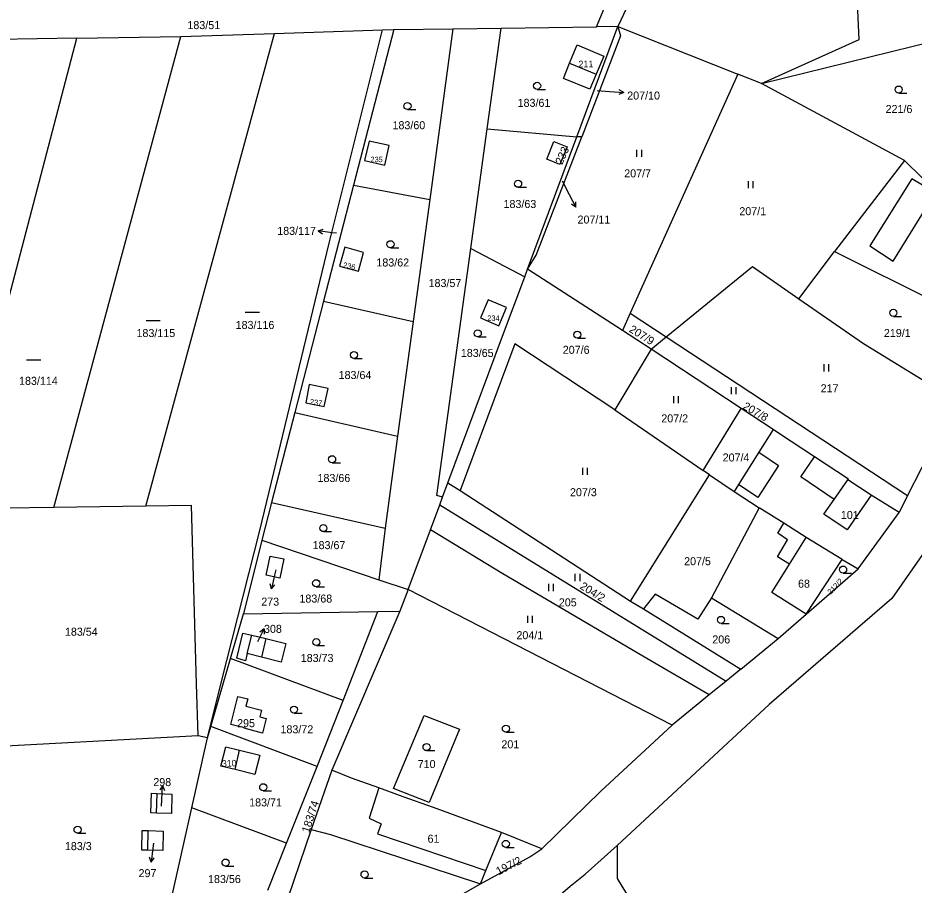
# Model space of a CAD drawing. Extents: x -7483133 to -743169, y -11317770 to -1127091.
# Drawn here: x -746832.8 to -746642.5, y -1132263.2 to -1132079.1 of the extents above; entities that cross this region are included whole.
import ezdxf

# ---------------------------------------------------------------- set-up
doc = ezdxf.new("R2010")
doc.units = 0
for name, color, linetype in [('Hranice parcel', 7, 'Continuous'), ('Parcelní čísla', 7, 'Continuous'), ('Pop  PČ popisy', 7, 'Continuous'), ('Vnitřní kresba', 7, 'Continuous'), ('Značky kultur', 7, 'Continuous')]:
    doc.layers.add(name, color=color, linetype=linetype)

msp = doc.modelspace()

# ---------------------------------------------------------------- linework, layer by layer
at = {"layer": 'Hranice parcel'}
for p, q in [((-746778.25, -1132082.36), (-746755.32, -1132081.61)), ((-746752.93, -1132081.53), (-746761.49, -1132114.56)), ((-746755.32, -1132081.61), (-746752.93, -1132081.53)), ((-746752.93, -1132081.53), (-746740.4, -1132081.38)), ((-746740.4, -1132081.38), (-746745.32, -1132117.64)), ((-746740.4, -1132081.38), (-746730.14, -1132081.25)), ((-746733.1, -1132102.66), (-746730.14, -1132081.25)), ((-746730.14, -1132081.25), (-746709.89, -1132080.97)), ((-746714.1, -1132104.36), (-746705.38, -1132080.91)), ((-746705.38, -1132080.91), (-746709.89, -1132080.97)), ((-746705.38, -1132080.91), (-746679.89, -1132091)), ((-746705.38, -1132080.91), (-746704.8, -1132082.86)), ((-746820.24, -1132083.39), (-746845.06, -1132083.8)), ((-746825.13, -1132182.99), (-746798.2, -1132083.02)), ((-746820.24, -1132083.39), (-746798.2, -1132083.02)), ((-746805.63, -1132182.7), (-746778.25, -1132082.36)), ((-746798.2, -1132083.02), (-746778.25, -1132082.36)), ((-746704.8, -1132082.86), (-746713.07, -1132104.3)), ((-746674.91, -1132092.97), (-746635.72, -1132083.37)), ((-746679.89, -1132091), (-746702.74, -1132141.73)), ((-746674.91, -1132092.97), (-746679.89, -1132091)), ((-746644.51, -1132109.35), (-746674.91, -1132092.97)), ((-746736.6, -1132128.06), (-746733.1, -1132102.66)), ((-746733.1, -1132102.66), (-746714.1, -1132104.36)), ((-746724.55, -1132132.39), (-746714.1, -1132104.36)), ((-746713.07, -1132104.3), (-746714.1, -1132104.36)), ((-746644.51, -1132109.35), (-746659.43, -1132128.69)), ((-746640.76, -1132113.05), (-746644.51, -1132109.35)), ((-746761.49, -1132114.56), (-746767.86, -1132139.21)), ((-746761.49, -1132114.56), (-746745.32, -1132117.64)), ((-746745.32, -1132117.64), (-746748.85, -1132143.55)), ((-746743.8, -1132180.44), (-746736.6, -1132128.06)), ((-746736.6, -1132128.06), (-746725.17, -1132134.06)), ((-746666.94, -1132138.69), (-746659.43, -1132128.69)), ((-746659.43, -1132128.69), (-746625.72, -1132145.44)), ((-746725.17, -1132134.06), (-746724.55, -1132132.39)), ((-746704.42, -1132145.46), (-746724.55, -1132132.39)), ((-746767.86, -1132139.21), (-746773.98, -1132162.83)), ((-746767.86, -1132139.21), (-746748.85, -1132143.55)), ((-746702.74, -1132141.73), (-746704.42, -1132145.46)), ((-746702.74, -1132141.73), (-746695.1, -1132146.75)), ((-746748.85, -1132143.55), (-746752.17, -1132167.89)), ((-746698.35, -1132149.4), (-746704.42, -1132145.46)), ((-746698.35, -1132149.4), (-746695.1, -1132146.75)), ((-746695.1, -1132146.75), (-746643.87, -1132180.43)), ((-746698.35, -1132149.4), (-746706, -1132162.26)), ((-746679.2, -1132162.02), (-746698.35, -1132149.4)), ((-746633.63, -1132160.23), (-746643.87, -1132180.43)), ((-746773.98, -1132162.83), (-746778.93, -1132181.95)), ((-746773.98, -1132162.83), (-746752.17, -1132167.89)), ((-746706, -1132162.26), (-746687.28, -1132175.19)), ((-746687.28, -1132175.19), (-746679.2, -1132162.02)), ((-746672.44, -1132166.48), (-746679.2, -1132162.02)), ((-746752.17, -1132167.89), (-746754.82, -1132187.37)), ((-746685.93, -1132176.1), (-746687.28, -1132175.19)), ((-746702.69, -1132202.89), (-746685.93, -1132176.1)), ((-746685.93, -1132176.1), (-746680.69, -1132179.58)), ((-746742.61, -1132180.85), (-746741.45, -1132177.74)), ((-746741.45, -1132177.74), (-746738.86, -1132179.39)), ((-746742.61, -1132180.85), (-746743.8, -1132180.44)), ((-746743.19, -1132182.42), (-746742.61, -1132180.85)), ((-746738.86, -1132179.39), (-746702.69, -1132202.89)), ((-746680.69, -1132179.58), (-746675.38, -1132183.11)), ((-746643.87, -1132180.43), (-746645.7, -1132184.06)), ((-746805.63, -1132182.7), (-746825.13, -1132182.99)), ((-746778.93, -1132181.95), (-746781, -1132189.93)), ((-746778.93, -1132181.95), (-746754.82, -1132187.37)), ((-746745.18, -1132187.75), (-746743.19, -1132182.42)), ((-746743.19, -1132182.42), (-746682.41, -1132219.89)), ((-746675.38, -1132183.11), (-746685.49, -1132202.16)), ((-746654.39, -1132196.03), (-746645.7, -1132184.06)), ((-746754.82, -1132187.37), (-746756.13, -1132198.33)), ((-746749.91, -1132200.43), (-746745.18, -1132187.75)), ((-746781, -1132189.93), (-746784.83, -1132205.6)), ((-746781, -1132189.93), (-746756.13, -1132198.33)), ((-746665.44, -1132205.68), (-746657.77, -1132194.04)), ((-746657.77, -1132194.04), (-746654.39, -1132196.03)), ((-746665.44, -1132205.68), (-746654.39, -1132196.03)), ((-746756.13, -1132198.33), (-746749.91, -1132200.43)), ((-746749.91, -1132200.43), (-746751.65, -1132205.03)), ((-746693.83, -1132229.18), (-746749.91, -1132200.43)), ((-746702.69, -1132202.89), (-746699.96, -1132204.52)), ((-746685.49, -1132202.16), (-746671.39, -1132210.8)), ((-746787.59, -1132215.05), (-746784.83, -1132205.6)), ((-746784.83, -1132205.6), (-746756.31, -1132205.11)), ((-746751.65, -1132205.03), (-746766.12, -1132238.78)), ((-746763.69, -1132223.97), (-746756.31, -1132205.11)), ((-746756.31, -1132205.11), (-746751.65, -1132205.03)), ((-746699.96, -1132204.52), (-746679.29, -1132217.36)), ((-746671.39, -1132210.8), (-746665.44, -1132205.68)), ((-746679.29, -1132217.36), (-746671.39, -1132210.8)), ((-746791.83, -1132229.53), (-746787.59, -1132215.05)), ((-746763.69, -1132223.97), (-746787.59, -1132215.05)), ((-746679.29, -1132217.36), (-746682.41, -1132219.89)), ((-746682.41, -1132219.89), (-746686, -1132222.81)), ((-746769.22, -1132238.01), (-746763.69, -1132223.97)), ((-746686, -1132222.81), (-746693.83, -1132229.18)), ((-746792.52, -1132231.9), (-746791.83, -1132229.53)), ((-746769.22, -1132238.01), (-746791.83, -1132229.53)), ((-746795.83, -1132246.75), (-746792.52, -1132231.9)), ((-746792.52, -1132231.9), (-746794.52, -1132231.47)), ((-746775.72, -1132254.29), (-746769.22, -1132238.01)), ((-746766.12, -1132238.78), (-746770.48, -1132251.33)), ((-746801.64, -1132272.79), (-746795.83, -1132246.75)), ((-746775.72, -1132254.29), (-746795.83, -1132246.75)), ((-746721.51, -1132255.46), (-746730.11, -1132251.98)), ((-746779.69, -1132264.25), (-746775.72, -1132254.29)), ((-746739.61, -1132265.77), (-746734.54, -1132262.91))]:
    msp.add_line(p, q, dxfattribs=at)
for points in [[(-746709.89, -1132080.97), (-746700.88, -1132059.24), (-746690.31, -1132034.95), (-746646.39, -1131931.6)], [(-746640.16, -1131931.3), (-746678.35, -1132019.74), (-746690.91, -1132050.15), (-746705.38, -1132080.91)], [(-746674.91, -1132092.97), (-746654.17, -1132083.68), (-746655.72, -1132049.5), (-746655.89, -1132035.79), (-746596.68, -1131997.54)], [(-746792.52, -1132231.9), (-746789.57, -1132220.24), (-746781.38, -1132187.88), (-746766.7, -1132126.93), (-746755.32, -1132081.61)], [(-746858.02, -1132224.47), (-746835.83, -1132142.89), (-746820.24, -1132083.39)], [(-746711.32, -1132094.22), (-746716.94, -1132091.93), (-746715.63, -1132088.71), (-746714.06, -1132084.83), (-746708.4, -1132087.18), (-746709.98, -1132090.99), (-746711.32, -1132094.22)], [(-746724.55, -1132132.39), (-746722.76, -1132129.43), (-746713.07, -1132104.3)], [(-746753.94, -1132106.19), (-746758.21, -1132105.23), (-746759.16, -1132109.33), (-746754.88, -1132110.32), (-746753.94, -1132106.19)], [(-746718.96, -1132105.32), (-746716.14, -1132106.48), (-746717.68, -1132110.21), (-746720.5, -1132109.04), (-746718.96, -1132105.32)], [(-746764.45, -1132131.77), (-746760.45, -1132132.87), (-746759.36, -1132128.86), (-746763.36, -1132127.77), (-746764.45, -1132131.77)], [(-746695.1, -1132146.75), (-746676.81, -1132131.86), (-746666.94, -1132138.69)], [(-746741.45, -1132177.74), (-746729.85, -1132146.61), (-746725.17, -1132134.06)], [(-746732.9, -1132138.91), (-746734.55, -1132142.77), (-746730.68, -1132144.42), (-746729.03, -1132140.57), (-746732.9, -1132138.91)], [(-746666.94, -1132138.69), (-746653.23, -1132148.18), (-746633.63, -1132160.23)], [(-746706, -1132162.26), (-746727.28, -1132148.3), (-746738.86, -1132179.39)], [(-746770.91, -1132156.92), (-746771.66, -1132160.8), (-746767.74, -1132161.56), (-746766.92, -1132157.72), (-746770.91, -1132156.92)], [(-746672.44, -1132166.48), (-746675.45, -1132171.26), (-746679.79, -1132178.16), (-746680.69, -1132179.58)], [(-746645.7, -1132184.06), (-746651.6, -1132180.37), (-746656.53, -1132177.13), (-746656.42, -1132176.97), (-746663.67, -1132172.26), (-746671.09, -1132167.37), (-746672.44, -1132166.48)], [(-746627.53, -1132169.14), (-746637.59, -1132188.53), (-746647.21, -1132202.3), (-746673.25, -1132224.8), (-746705.52, -1132254.75)], [(-746794.52, -1132231.47), (-746794.83, -1132220.45), (-746795.89, -1132182.56), (-746805.63, -1132182.7)], [(-746825.13, -1132182.99), (-746845.75, -1132183.3), (-746844.91, -1132224.19)], [(-746657.77, -1132194.04), (-746665.4, -1132189.36), (-746670.13, -1132186.36), (-746675.38, -1132183.11)], [(-746686, -1132222.81), (-746700.07, -1132214.57), (-746729.82, -1132197.08), (-746745.18, -1132187.75)], [(-746779.23, -1132193.32), (-746776.31, -1132193.91), (-746777.12, -1132197.98), (-746780.05, -1132197.37), (-746779.23, -1132193.32)], [(-746685.49, -1132202.16), (-746688.44, -1132206.74), (-746697.45, -1132201.42), (-746699.96, -1132204.52)], [(-746783.07, -1132210.11), (-746780.12, -1132210.8), (-746775.87, -1132211.89), (-746776.88, -1132215.82), (-746781.07, -1132214.77), (-746784.07, -1132214.03), (-746784.43, -1132215.59), (-746786.31, -1132214.99), (-746785, -1132209.67), (-746783.07, -1132210.11)], [(-746794.52, -1132231.47), (-746844.62, -1132234.18), (-746844.91, -1132224.19)], [(-746780.82, -1132230.88), (-746784.71, -1132229.88), (-746784.68, -1132229.78), (-746787.58, -1132229.04), (-746786.06, -1132223.12), (-746783.97, -1132223.66), (-746784.36, -1132225.19), (-746781.01, -1132226.05), (-746781.38, -1132227.48), (-746780.03, -1132227.83), (-746780.82, -1132230.88)], [(-746746.53, -1132227.19), (-746739, -1132230.07), (-746745.42, -1132245.64), (-746753.02, -1132242.69), (-746746.53, -1132227.19)], [(-746721.51, -1132255.46), (-746709.03, -1132243.21), (-746693.83, -1132229.18)], [(-746785.69, -1132234.52), (-746781.4, -1132235.6), (-746782.44, -1132239.69), (-746786.66, -1132238.64), (-746789.66, -1132237.89), (-746788.62, -1132233.78), (-746785.69, -1132234.52)], [(-746730.11, -1132251.98), (-746744.54, -1132246.69), (-746750.97, -1132244.4), (-746756.12, -1132242.54), (-746761.95, -1132240.48), (-746766.12, -1132238.78)], [(-746803.22, -1132243.72), (-746800.06, -1132243.84), (-746800.18, -1132248), (-746803.33, -1132247.87), (-746804.5, -1132247.82), (-746804.37, -1132243.68), (-746803.22, -1132243.72)], [(-746801.92, -1132251.69), (-746801.99, -1132255.84), (-746805.19, -1132255.76), (-746806.42, -1132255.73), (-746806.38, -1132251.58), (-746805.12, -1132251.61), (-746801.92, -1132251.69)], [(-746770.48, -1132251.33), (-746776.66, -1132269.51), (-746771.04, -1132270.84)], [(-746770.48, -1132251.33), (-746766.36, -1132252.44), (-746734.54, -1132262.91)], [(-746734.54, -1132262.91), (-746733.4, -1132260.05), (-746730.11, -1132251.98)], [(-746733.81, -1132276.07), (-746730.72, -1132274.13), (-746718.09, -1132265.55), (-746715.48, -1132263.41), (-746712.32, -1132260.82), (-746705.52, -1132254.75)], [(-746705.52, -1132254.75), (-746705.52, -1132261.75), (-746702.56, -1132266.68), (-746651.51, -1132285.68), (-746635.38, -1132289.23)], [(-746734.54, -1132262.91), (-746724.11, -1132257.19), (-746721.51, -1132255.46)]]:
    msp.add_lwpolyline(points, dxfattribs=at)
at = {"layer": 'Pop  PČ popisy'}
for p, q in [((-746709.8, -1132094.52), (-746707.14, -1132094.71)), ((-746707.14, -1132094.71), (-746704.15, -1132094.92)), ((-746704.15, -1132094.92), (-746705.18, -1132095.35)), ((-746704.15, -1132094.92), (-746705.11, -1132094.35)), ((-746717.22, -1132113.7), (-746715.7, -1132116.6)), ((-746715.7, -1132116.6), (-746714.29, -1132119.25)), ((-746714.29, -1132119.25), (-746714.32, -1132118.13)), ((-746714.29, -1132119.25), (-746715.2, -1132118.6)), ((-746769.02, -1132124.26), (-746767.96, -1132123.91)), ((-746766.05, -1132124.68), (-746769.02, -1132124.26)), ((-746769.02, -1132124.26), (-746768.1, -1132124.9)), ((-746765.15, -1132124.8), (-746766.05, -1132124.68)), ((-746778.25, -1132197.36), (-746778.93, -1132200.28)), ((-746777.98, -1132196.22), (-746778.25, -1132197.36)), ((-746778.93, -1132200.28), (-746779.19, -1132199.2)), ((-746778.93, -1132200.28), (-746778.21, -1132199.42)), ((-746781.83, -1132211.46), (-746780.51, -1132208.76)), ((-746780.51, -1132208.76), (-746781.4, -1132209.44)), ((-746780.51, -1132208.76), (-746780.5, -1132209.88)), ((-746802.05, -1132242.04), (-746802.6, -1132243.02)), ((-746802.21, -1132245.04), (-746802.05, -1132242.04)), ((-746802.05, -1132242.04), (-746801.6, -1132243.07)), ((-746802.29, -1132246.38), (-746802.21, -1132245.04)), ((-746803.94, -1132254.29), (-746804.08, -1132255.35)), ((-746804.08, -1132255.35), (-746804.45, -1132258.33)), ((-746804.45, -1132258.33), (-746804.82, -1132257.27)), ((-746804.45, -1132258.33), (-746803.83, -1132257.4))]:
    msp.add_line(p, q, dxfattribs=at)
at = {"layer": 'Vnitřní kresba'}
for p, q in [((-746715.63, -1132088.71), (-746709.98, -1132090.99)), ((-746642.98, -1132113.24), (-746651.88, -1132127.45)), ((-746637.99, -1132116.23), (-746642.98, -1132113.24)), ((-746646.97, -1132130.75), (-746637.99, -1132116.23)), ((-746651.88, -1132127.45), (-746646.97, -1132130.75)), ((-746675.45, -1132171.26), (-746671.27, -1132174.11)), ((-746666.56, -1132176.49), (-746663.67, -1132172.26)), ((-746671.27, -1132174.11), (-746675.65, -1132180.87)), ((-746659.47, -1132181.31), (-746666.56, -1132176.49)), ((-746675.65, -1132180.87), (-746679.79, -1132178.16)), ((-746659.47, -1132181.31), (-746656.53, -1132177.13)), ((-746651.6, -1132180.37), (-746656.68, -1132187.78)), ((-746661.63, -1132184.39), (-746659.47, -1132181.31)), ((-746656.68, -1132187.78), (-746661.63, -1132184.39)), ((-746671.46, -1132188.47), (-746670.13, -1132186.36)), ((-746669.35, -1132189.9), (-746671.46, -1132188.47)), ((-746671.5, -1132193.47), (-746669.35, -1132189.9)), ((-746668.98, -1132195.04), (-746665.4, -1132189.36)), ((-746668.98, -1132195.04), (-746671.5, -1132193.47)), ((-746672.69, -1132201.07), (-746668.98, -1132195.04)), ((-746665.44, -1132205.68), (-746672.69, -1132201.07)), ((-746784.07, -1132214.03), (-746783.07, -1132210.11)), ((-746780.12, -1132210.8), (-746781.07, -1132214.77)), ((-746786.66, -1132238.64), (-746785.69, -1132234.52)), ((-746756.12, -1132242.54), (-746758.19, -1132248.97)), ((-746803.33, -1132247.87), (-746803.22, -1132243.72)), ((-746758.19, -1132248.97), (-746755.61, -1132250.15)), ((-746755.61, -1132250.15), (-746756.42, -1132252.29)), ((-746805.19, -1132255.76), (-746805.12, -1132251.61)), ((-746756.42, -1132252.29), (-746733.4, -1132260.05))]:
    msp.add_line(p, q, dxfattribs=at)
at = {"layer": 'Značky kultur'}
for p, q in [((-746722.52, -1132094.25), (-746720.77, -1132094.25)), ((-746645.77, -1132095.04), (-746644.02, -1132095.04)), ((-746750.05, -1132098.54), (-746748.3, -1132098.54)), ((-746701.33, -1132108.56), (-746701.33, -1132107.06)), ((-746700.33, -1132108.56), (-746700.33, -1132107.06)), ((-746677.68, -1132115.25), (-746677.68, -1132113.75)), ((-746676.68, -1132115.25), (-746676.68, -1132113.75)), ((-746726.56, -1132115.04), (-746724.81, -1132115.04)), ((-746753.66, -1132127.87), (-746751.91, -1132127.87)), ((-746784.5, -1132141.56), (-746781.5, -1132141.56)), ((-746646.9, -1132142.44), (-746645.15, -1132142.44)), ((-746805.52, -1132143.28), (-746802.52, -1132143.28)), ((-746735.13, -1132146.8), (-746733.38, -1132146.8)), ((-746713.99, -1132147.08), (-746712.24, -1132147.08)), ((-746830.92, -1132151.63), (-746827.92, -1132151.63)), ((-746761.41, -1132151.38), (-746759.66, -1132151.38)), ((-746661.58, -1132154.11), (-746661.58, -1132152.61)), ((-746660.58, -1132154.11), (-746660.58, -1132152.61)), ((-746681.27, -1132158.98), (-746681.27, -1132157.48)), ((-746680.27, -1132158.98), (-746680.27, -1132157.48)), ((-746693.52, -1132160.87), (-746693.52, -1132159.37)), ((-746692.52, -1132160.87), (-746692.52, -1132159.37)), ((-746766.05, -1132173.51), (-746764.3, -1132173.51)), ((-746712.83, -1132176.07), (-746712.83, -1132174.57)), ((-746711.83, -1132176.07), (-746711.83, -1132174.57)), ((-746767.9, -1132188.13), (-746766.15, -1132188.13)), ((-746714.42, -1132198.62), (-746714.42, -1132197.12)), ((-746713.42, -1132198.62), (-746713.42, -1132197.12)), ((-746657.57, -1132196.93), (-746655.82, -1132196.93)), ((-746769.43, -1132199.84), (-746767.68, -1132199.84)), ((-746720.06, -1132200.74), (-746720.06, -1132199.24)), ((-746719.06, -1132200.74), (-746719.06, -1132199.24)), ((-746724.48, -1132207.5), (-746724.48, -1132206)), ((-746723.48, -1132207.5), (-746723.48, -1132206)), ((-746683.49, -1132207.62), (-746681.74, -1132207.62)), ((-746769.4, -1132212.32), (-746767.65, -1132212.32)), ((-746774.14, -1132226.66), (-746772.39, -1132226.66)), ((-746729.16, -1132230.7), (-746727.41, -1132230.7)), ((-746746, -1132234.62), (-746744.25, -1132234.62)), ((-746780.68, -1132243.14), (-746778.93, -1132243.14)), ((-746820.09, -1132252.15), (-746818.34, -1132252.15)), ((-746729.17, -1132255.17), (-746727.42, -1132255.17)), ((-746788.67, -1132259.13), (-746786.92, -1132259.13)), ((-746759.16, -1132261.66), (-746757.41, -1132261.66))]:
    msp.add_line(p, q, dxfattribs=at)
for centre in [(-746722.52, -1132093.5), (-746645.77, -1132094.29), (-746750.05, -1132097.79), (-746726.56, -1132114.29), (-746753.66, -1132127.12), (-746646.9, -1132141.69), (-746735.13, -1132146.05), (-746713.99, -1132146.33), (-746761.41, -1132150.63), (-746766.05, -1132172.76), (-746767.9, -1132187.38), (-746657.57, -1132196.18), (-746769.43, -1132199.09), (-746683.49, -1132206.87), (-746769.4, -1132211.57), (-746774.14, -1132225.91), (-746729.16, -1132229.95), (-746746, -1132233.87), (-746780.68, -1132242.39), (-746820.09, -1132251.4), (-746729.17, -1132254.42), (-746788.67, -1132258.38), (-746759.16, -1132260.91)]:
    msp.add_circle(centre, 0.75, dxfattribs=at)

# ---------------------------------------------------------------- texts
at = {"layer": 'Parcelní čísla'}
for s, height, p in [('183/51', 1.7, (-746796.77, -1132081.46)), ('207/10', 1.7, (-746703.4, -1132096.41)), ('183/61', 1.7, (-746726.67, -1132097.96)), ('221/6', 1.7, (-746648.55, -1132099.27)), ('183/60', 1.7, (-746753.23, -1132102.71)), ('235', 1.14, (-746757.92, -1132109.7)), ('207/7', 1.7, (-746704.04, -1132112.93)), ('183/63', 1.7, (-746729.66, -1132119.43)), ('207/1', 1.7, (-746679.6, -1132120.96)), ('207/11', 1.7, (-746713.95, -1132122.74)), ('183/117', 1.7, (-746777.7, -1132125.14)), ('183/62', 1.7, (-746756.65, -1132131.85)), ('183/57', 1.7, (-746745.57, -1132136.22)), ('234', 1.14, (-746733.11, -1132143.39)), ('183/116', 1.7, (-746786.53, -1132145.11)), ('183/115', 1.7, (-746807.58, -1132146.83)), ('219/1', 1.7, (-746648.91, -1132146.82)), ('183/65', 1.7, (-746738.72, -1132151.05)), ('207/6', 1.7, (-746717.08, -1132150.39)), ('183/64', 1.7, (-746764.67, -1132155.74)), ('183/114', 1.7, (-746832.51, -1132156.97)), ('217', 1.7, (-746662.34, -1132158.55)), ('207/2', 1.7, (-746696.16, -1132164.94)), ('207/4', 1.7, (-746683.14, -1132173.24)), ('183/66', 1.7, (-746769.15, -1132177.6)), ('207/3', 1.7, (-746715.55, -1132180.61)), ('101', 1.7, (-746658.05, -1132185.45)), ('183/67', 1.7, (-746770.19, -1132191.85)), ('207/5', 1.7, (-746691.32, -1132195.26)), ('68', 1.7, (-746667.14, -1132200.03)), ('183/68', 1.7, (-746772.99, -1132203.19)), ('273', 1.7, (-746781.09, -1132203.84)), ('205', 1.7, (-746717.92, -1132204)), ('183/54', 1.7, (-746822.77, -1132210.23)), ('308', 1.7, (-746780.51, -1132209.62)), ('204/1', 1.7, (-746726.92, -1132210.97)), ('206', 1.7, (-746685.34, -1132211.87)), ('183/73', 1.7, (-746772.71, -1132215.8)), ('295', 1.7, (-746786.22, -1132229.64)), ('183/72', 1.7, (-746777.01, -1132230.94)), ('201', 1.7, (-746730.11, -1132234.13)), ('710', 1.7, (-746747.88, -1132238.32)), ('298', 1.7, (-746804.01, -1132242.15)), ('183/71', 1.7, (-746783.66, -1132246.46)), ('61', 1.7, (-746745.79, -1132254.17)), ('183/3', 1.7, (-746822.78, -1132255.74)), ('297', 1.7, (-746807.14, -1132261.48)), ('183/56', 1.7, (-746792.39, -1132262.73))]:
    msp.add_text(s, height=height, dxfattribs=at).set_placement(p)
for s, height, rotation, p in [('211', 1.436, 1, (-746713.76, -1132089.61)), ('233', 1.7, 66, (-746717.22, -1132110.36)), ('236', 1.14, 348, (-746763.81, -1132132.04)), ('207/9', 1.7, 328, (-746703.16, -1132145.61)), ('237', 1.14, 352, (-746770.83, -1132161.09)), ('207/8', 1.7, 330, (-746679.02, -1132161.97)), ('204/2', 1.7, 328, (-746713.59, -1132200.13)), ('212/2', 1.14, 46, (-746660.21, -1132201.57)), ('310', 1.386, 2, (-746789.43, -1132238.06)), ('183/74', 1.7, 72, (-746770.95, -1132252.19)), ('197/2', 1.7, 27, (-746730.71, -1132261.1))]:
    msp.add_text(s, height=height, rotation=rotation, dxfattribs=at).set_placement(p)

doc.saveas('drawing.dxf')
